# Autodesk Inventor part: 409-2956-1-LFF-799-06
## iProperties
Created: 2010-11
Part Number: 409-2956-1-LFF-799-06
Material: 3/4" OD TUBE - SS
Document SubType Name: Modeling
Designer: S. Boerckel
Engineer: Steve Boerckel
Mass: 340.704 g
Surface Area: 512.603 cm^2
Volume: 42.1664 cm^3
Density: 8.08 g/cm^3
Description: DRAIN TUBING
Length: 17.945 in
Author: S. Boerckel
Revision Number: 0
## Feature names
1. Sweep2
